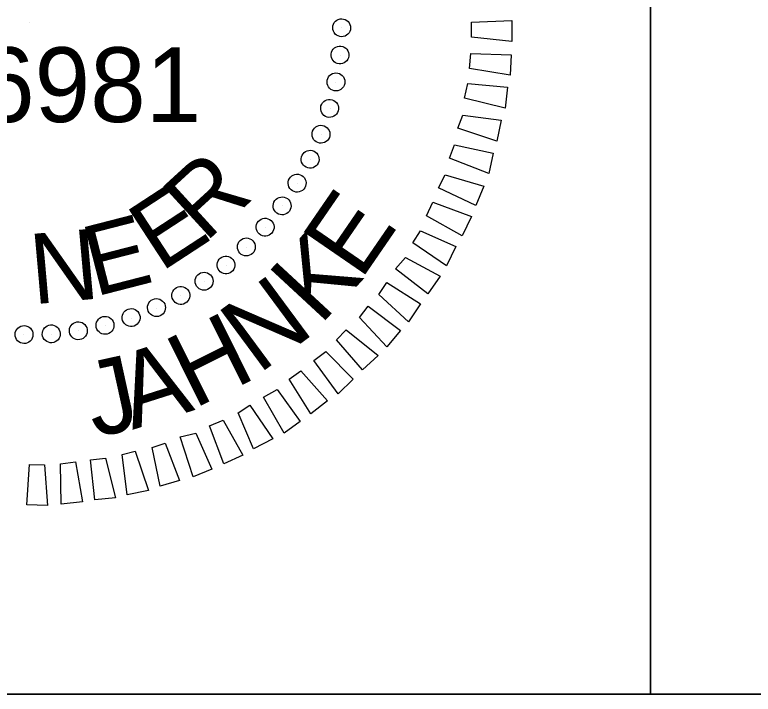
# Model space of a CAD drawing. Extents: x 3025871 to 3026431, y 707165 to 707825.
# Drawn here: x 3026249.41 to 3026258.31, y 707710.95 to 707719.14 of the extents above; entities that cross this region are included whole.
import ezdxf

# ---------------------------------------------------------------- set-up
doc = ezdxf.new("R2010")
doc.units = 0
for name, color, linetype in [('Old_Level_19', 7, 'Continuous'), ('Sheet Block Title CELL', 7, 'Continuous'), ('Sheet Cutting Line CELL', 7, 'Continuous')]:
    doc.layers.add(name, color=color, linetype=linetype)

msp = doc.modelspace()

# ---------------------------------------------------------------- linework, layer by layer
at = {"layer": 'Old_Level_19'}
msp.add_line((3026242.0652, 707710.953), (3026272.0708, 707710.953), dxfattribs=at)
at = {"layer": 'Sheet Block Title CELL'}
for p, q in [((3026249.5907, 707719.0475), (3026249.5907, 707719.0475)), ((3026253.3557, 707718.98), (3026253.3557, 707718.98)), ((3026253.3332, 707718.65), (3026253.3332, 707718.65)), ((3026253.2807, 707718.3275), (3026253.2807, 707718.3275)), ((3026253.2132, 707718.0125), (3026253.2132, 707718.0125)), ((3026253.1082, 707717.6975), (3026253.1082, 707717.6975)), ((3026252.9732, 707717.3975), (3026252.9732, 707717.3975)), ((3026252.8232, 707717.105), (3026252.8232, 707717.105)), ((3026252.6357, 707716.835), (3026252.6357, 707716.835)), ((3026252.4332, 707716.5725), (3026252.4332, 707716.5725)), ((3026252.2082, 707716.34), (3026252.2082, 707716.34)), ((3026251.9607, 707716.115), (3026251.9607, 707716.115)), ((3026251.6982, 707715.9275), (3026251.6982, 707715.9275)), ((3026251.4132, 707715.755), (3026251.4132, 707715.755)), ((3026251.1207, 707715.605), (3026251.1207, 707715.605)), ((3026250.8207, 707715.485), (3026250.8207, 707715.485)), ((3026250.5057, 707715.395), (3026250.5057, 707715.395)), ((3026249.5232, 707715.2825), (3026249.5232, 707715.2825)), ((3026249.8532, 707715.29), (3026249.8532, 707715.29)), ((3026250.1757, 707715.335), (3026250.1757, 707715.335))]:
    msp.add_line(p, q, dxfattribs=at)
for points in [[(3026254.9157, 707719.0475), (3026255.4032, 707719.07), (3026255.4032, 707718.815), (3026254.9157, 707718.8675)], [(3026254.9082, 707718.6725), (3026255.3957, 707718.6575), (3026255.3807, 707718.41), (3026254.8932, 707718.4925)], [(3026254.8707, 707718.3125), (3026255.3507, 707718.2675), (3026255.3207, 707718.0125), (3026254.8332, 707718.1325)], [(3026254.8107, 707717.93), (3026255.2757, 707717.87), (3026255.2232, 707717.615), (3026254.7507, 707717.7725)], [(3026254.7132, 707717.57), (3026255.1782, 707717.4725), (3026255.1257, 707717.225), (3026254.6532, 707717.4125)], [(3026254.6007, 707717.21), (3026255.0657, 707717.075), (3026254.9682, 707716.8425), (3026254.5182, 707717.0525)], [(3026254.4507, 707716.88), (3026254.9157, 707716.7075), (3026254.8032, 707716.475), (3026254.3757, 707716.715)], [(3026254.3007, 707716.535), (3026254.7282, 707716.3475), (3026254.6157, 707716.115), (3026254.2107, 707716.3925)], [(3026254.1207, 707716.2125), (3026254.5407, 707715.9875), (3026254.3907, 707715.7775), (3026254.0007, 707716.0775)], [(3026253.8957, 707715.9125), (3026254.3007, 707715.6575), (3026254.1582, 707715.44), (3026253.7982, 707715.77)], [(3026253.6707, 707715.6275), (3026254.0607, 707715.335), (3026253.8957, 707715.14), (3026253.5657, 707715.4925)], [(3026253.4082, 707715.3425), (3026253.7907, 707715.035), (3026253.6032, 707714.8625), (3026253.2882, 707715.2225)], [(3026253.1607, 707715.08), (3026253.4907, 707714.75), (3026253.3107, 707714.57), (3026253.0182, 707714.975)], [(3026252.8607, 707714.8475), (3026253.1832, 707714.4875), (3026252.9807, 707714.33), (3026252.7182, 707714.75)], [(3026252.5757, 707714.6225), (3026252.8532, 707714.24), (3026252.6582, 707714.0975), (3026252.4107, 707714.5325)], [(3026252.2457, 707714.435), (3026252.5232, 707714.03), (3026252.2907, 707713.91), (3026252.1032, 707714.345)], [(3026251.9232, 707714.255), (3026252.1632, 707713.835), (3026251.9307, 707713.73), (3026251.7582, 707714.1875)], [(3026251.5932, 707714.0975), (3026251.7882, 707713.6625), (3026251.5632, 707713.5725), (3026251.4057, 707714.0525)], [(3026251.2257, 707713.9775), (3026251.3982, 707713.5275), (3026251.1657, 707713.46), (3026251.0682, 707713.925)], [(3026250.8657, 707713.88), (3026251.0232, 707713.4075), (3026250.7682, 707713.355), (3026250.7082, 707713.8425)], [(3026250.1457, 707713.7525), (3026250.2282, 707713.2725), (3026249.9732, 707713.2425), (3026249.9657, 707713.73)], [(3026250.5057, 707713.7975), (3026250.6257, 707713.3175), (3026250.3782, 707713.295), (3026250.3257, 707713.775)], [(3026249.7707, 707713.715), (3026249.8082, 707713.2275), (3026249.5607, 707713.235), (3026249.5907, 707713.7225)]]:
    msp.add_lwpolyline(points, close=True, dxfattribs=at)
for centre, major_axis in [((3026253.3522, 707718.9818), (0.108, -0.0019)), ((3026253.3321, 707718.6543), (0.1074, -0.0113)), ((3026253.2836, 707718.3297), (0.106, -0.0206)), ((3026253.207, 707718.0105), (0.1038, -0.0298)), ((3026253.1029, 707717.6993), (0.1008, -0.0387)), ((3026252.972, 707717.3983), (0.0971, -0.0473)), ((3026252.8154, 707717.1099), (0.0926, -0.0556)), ((3026252.6343, 707716.8362), (0.0874, -0.0635)), ((3026252.43, 707716.5794), (0.0815, -0.0709)), ((3026252.204, 707716.3413), (0.075, -0.0777)), ((3026251.9582, 707716.1239), (0.068, -0.0839)), ((3026251.6944, 707715.9287), (0.0604, -0.0895)), ((3026251.4146, 707715.7572), (0.0524, -0.0945)), ((3026251.1209, 707715.6107), (0.0439, -0.0987)), ((3026250.8155, 707715.4904), (0.0352, -0.1021)), ((3026250.1792, 707715.3318), (0.0169, -0.1067)), ((3026250.5008, 707715.3972), (0.0261, -0.1048)), ((3026249.5251, 707715.2861), (-0.0019, -0.108)), ((3026249.8532, 707715.2947), (0.0075, -0.1077))]:
    msp.add_ellipse(centre, major_axis=major_axis, ratio=0.999708, dxfattribs=at)
at = {"layer": 'Sheet Cutting Line CELL'}
msp.add_line((3026257.0727, 707727.828), (3026257.0727, 707710.9605), dxfattribs=at)
for points in [[(3026242.0652, 707727.828), (3026257.0727, 707727.828), (3026257.0727, 707710.953), (3026242.0652, 707710.953)], [(3026257.0727, 707727.828), (3026272.0727, 707727.828), (3026272.0727, 707710.953), (3026257.0727, 707710.953)]]:
    msp.add_lwpolyline(points, close=True, dxfattribs=at)

# ---------------------------------------------------------------- texts
at = {"layer": 'Sheet Block Title CELL'}
msp.add_text('046981', height=0.89973, dxfattribs=at).set_placement((3026247.6451, 707717.8462))
for s, height, rotation, p in [('R', 0.8458, 42.48141, (3026251.7057, 707716.385)), ('E', 0.8458, 33.12409, (3026251.1732, 707716.0325)), ('E', 0.8997, 55.49302, (3026253.5811, 707715.9287)), ('E', 0.8457, 14.41176, (3026250.3782, 707715.74)), ('N', 0.8457, 5.05639, (3026249.6357, 707715.65)), ('K', 0.8997, 47.2091, (3026253.0901, 707715.3863)), ('N', 0.8997, 36.48327, (3026252.3476, 707714.799)), ('H', 0.8997, 26.49929, (3026251.5692, 707714.3854)), ('A', 0.8997, 17.65898, (3026250.8293, 707714.1367)), ('J', 0.8997, 12.40116, (3026250.374, 707714.0439))]:
    msp.add_text(s, height=height, rotation=rotation, dxfattribs=at).set_placement(p)

doc.saveas('drawing.dxf')
